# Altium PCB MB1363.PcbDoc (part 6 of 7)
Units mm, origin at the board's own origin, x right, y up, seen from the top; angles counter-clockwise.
Board outline 70 x 133.34 mm, 6 copper layers (Top Layer, Signal Layer 1, Signal Layer 2, Signal Layer 3, Signal Layer 4, Bottom Layer), stack 1.57 mm thick; 356 components, 294 nets, 1448 pads, 1107 vias.
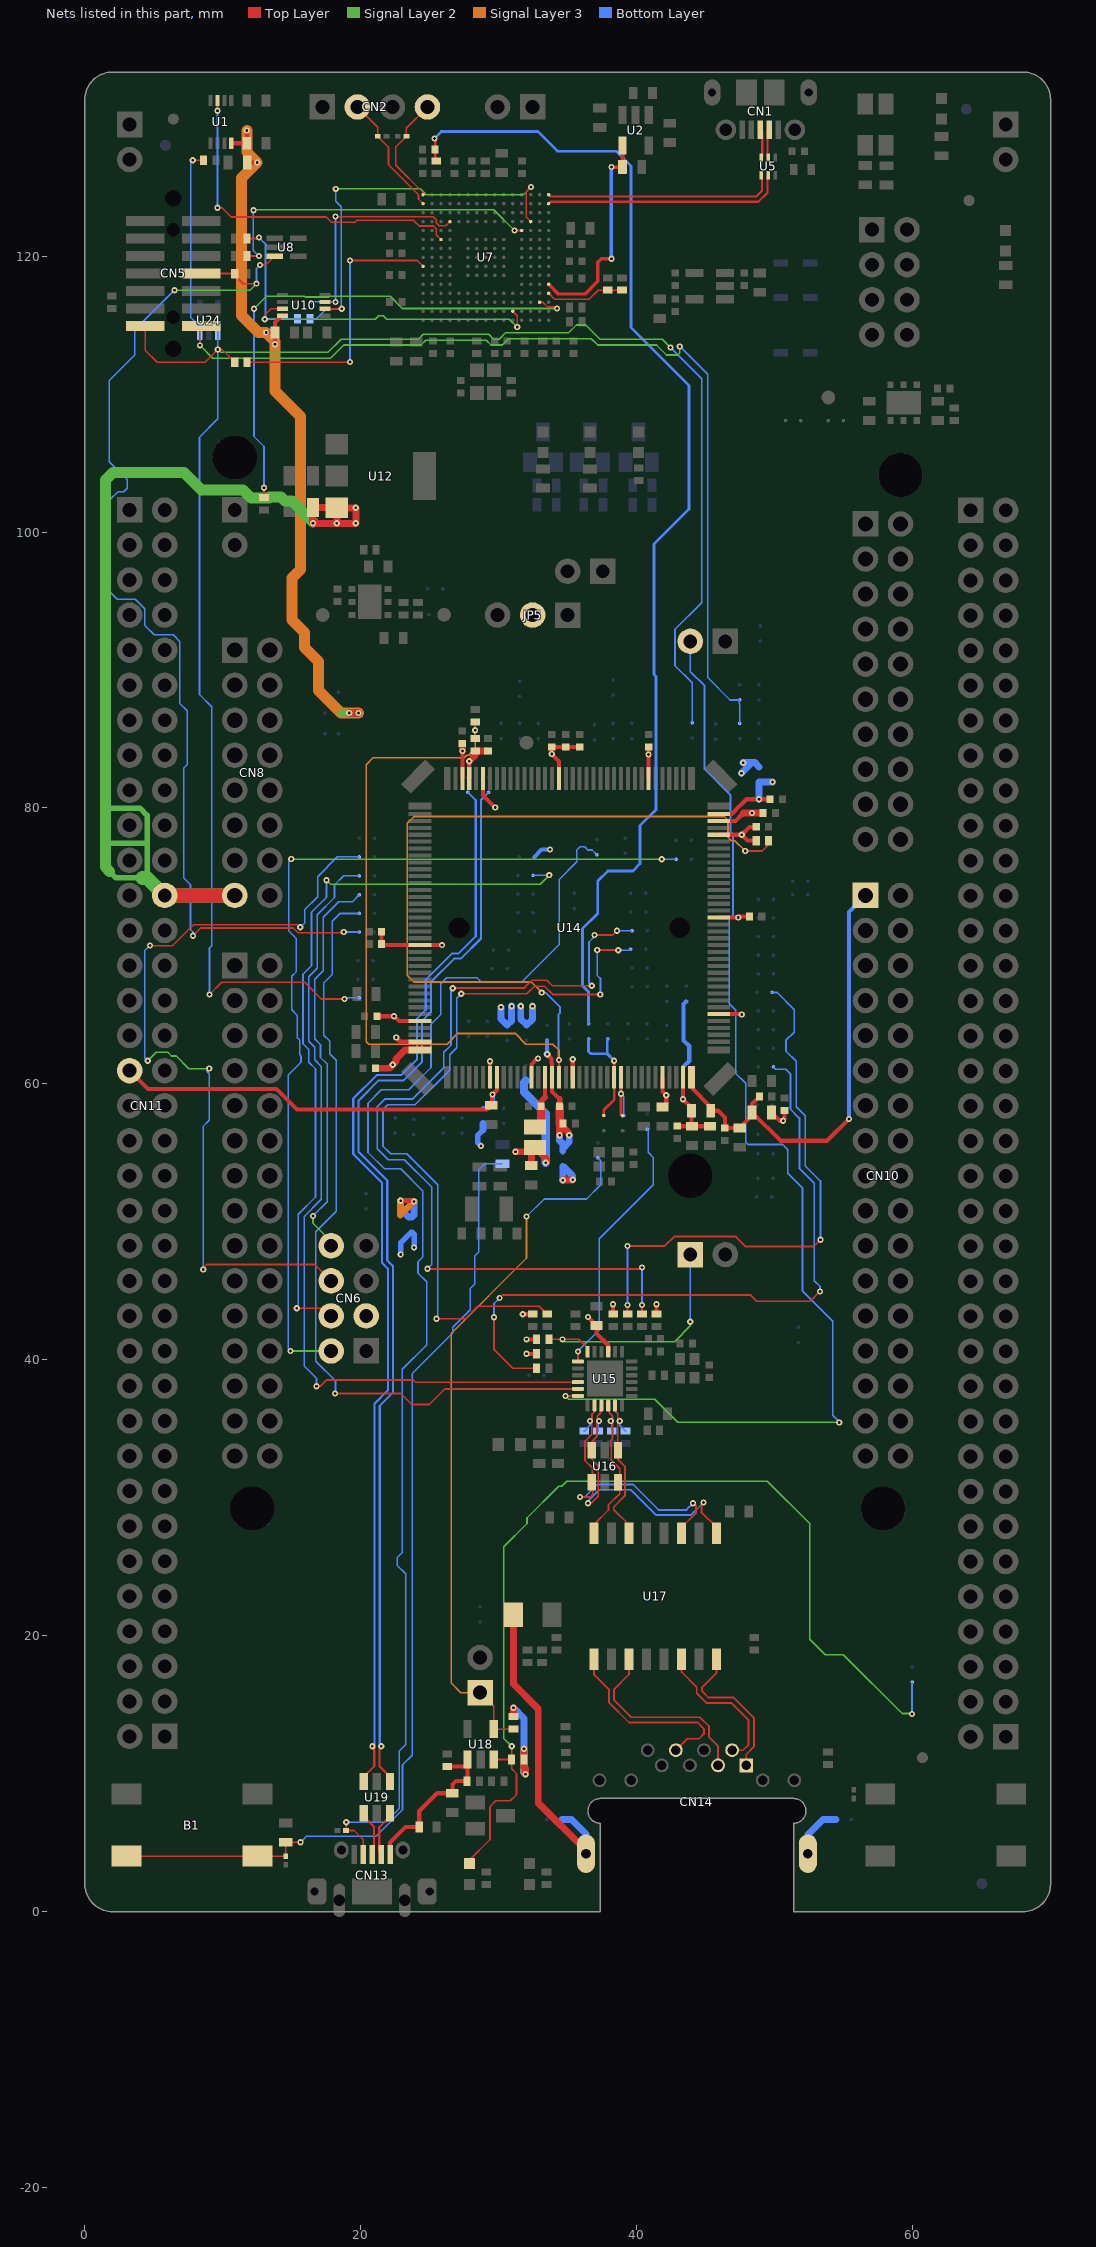
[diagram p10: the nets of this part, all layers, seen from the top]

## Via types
v1: diameter 0.45, hole 0.2, Top Layer to Bottom Layer, tented both sides, 1098 vias
v2: diameter 0.6, hole 0.3, Top Layer to Bottom Layer, tented both sides, 9 vias

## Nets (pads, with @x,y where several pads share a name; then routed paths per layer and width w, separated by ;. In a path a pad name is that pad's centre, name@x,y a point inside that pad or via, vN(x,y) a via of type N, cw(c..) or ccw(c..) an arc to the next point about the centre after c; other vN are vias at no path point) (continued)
PH0: SB3.1 SB71.1 SB72.1 U14.25 | length 8.4
  Top Layer w0.2: SB3.1@37.616,57.704 37.616,58.091 38.366,58.841 U14.25@38.366,60.479 v1(38.366,61.679)
  Bottom Layer w0.2: SB72.1@36.516,63.254 36.516,62.354 36.691,62.179 37.866,62.179 ; SB71.1@37.916,63.254 37.866,63.204 37.866,62.179 ; v1(38.366,61.679) 37.866,62.179
PH1: SB4.1 SB90.1 U14.26 | length 4.6
  Top Layer w0.127: U14.26@38.816,60.429 U14.26@38.866,60.479 ; 38.866,57.804 SB4.1@38.966,57.704
  Top Layer w0.2: 38.866,57.804 U14.26@38.866,60.479
  Signal Layer 2 w0.127: v1@38.866,59.176 v1(38.866,59.279)
  Bottom Layer w0.127: v1(38.866,59.279) 39.066,59.079 SB90.1@39.066,57.704
RD_N: R79.1 U15.22 U16.6 U17.8 | length 11.5
  Top Layer w0.11: 38.166,32.705 38.166,34.204
  Top Layer w0.13: U17.8@36.901,27.434 36.966,27.499 36.966,28.116 37.959,29.109 37.959,29.484 38.766,30.291 38.766,31.004 U16.6@38.641,31.129 38.766,31.254 38.766,32.105 38.166,32.705 ; U15.22@37.941,36.679 38.009,36.611 38.009,36.161 38.241,35.929 38.241,35.679 v1(38.116,35.554) 38.25,35.42 38.25,34.288 38.166,34.204
  Bottom Layer w0.13: R79.1@38.191,34.829 38.191,35.479 v1(38.116,35.554) v1@38.25,35.554
RD_P: R78.1 U15.23 U16.1 U17.6 | length 11.4
  Top Layer w0.13: U15.23@38.441,36.679 38.391,36.629 38.391,36.319 38.623,36.087 38.623,35.697 v1(38.766,35.554) 38.632,35.42 38.632,33.438 U16.1@38.641,33.429 38.641,32.781 39.148,32.274 39.148,30.133 38.341,29.326 38.341,29.134 39.441,28.034 U17.6@39.441,27.434
  Bottom Layer w0.13: v1(38.766,35.554) 38.766,35.254 R78.1@39.191,34.829
RMII_CRS_DV: R44.1 SB52.2 | length 54.4
  Top Layer w0.127: v1(25.491,42.979) 27.59,42.979 28.49,43.879 32.941,43.879 R44.1@33.516,43.304 ; v1(27.291,66.529) 32.041,66.529 32.591,67.079 33.316,67.079 33.914,66.481 34.418,66.481 34.42,66.479 v1(37.366,66.479) ; v1(37.141,69.704) 38.642,69.704 v1(38.667,69.68)
  Bottom Layer w0.127: v1(25.491,42.979) 25.572,43.06 25.572,52.698 23.341,54.929 22.166,54.929 21.616,55.479 21.616,58.152 21.943,58.479 23.935,58.479 26.443,60.987 26.443,62.102 26.966,62.626 26.966,66.204 v1(27.291,66.529) ; v1(37.141,69.704) 37.141,67.854 37.386,67.609 37.386,66.498 v1(37.366,66.479) ; v1(38.667,69.68) 39.492,69.68 SB52.2@39.566,69.754
RMII_MDC: SB84.1 U15.13 | length 19.3
  Top Layer w0.127: U15.13@35.741,39.879 v1(35.741,40.604)
  Bottom Layer w0.127: v1(35.741,40.604) 37.291,42.154 37.291,48.779 41.205,52.693 41.205,54.665 40.841,55.029 40.841,56.629 SB84.1@40.766,56.704
RMII_MDIO: JP7.1 R50.1 U15.12 | length 18.3
  Top Layer w0.127: R50.1@33.641,41.479 v1(34.616,41.479) 35.787,41.479 36.441,40.825 U15.12@36.441,40.579
  Signal Layer 2 w0.102: v1(34.616,41.479) 34.775,41.32 42.758,41.32 43.886,42.449 v1(43.886,42.749)
  Bottom Layer w0.127: v1(43.886,42.749) JP7.1@43.886,47.624
RMII_REF_CLK: R52.1 SB80.2 | length 49.4
  Top Layer w0.127: v1(29.666,43.079) 29.666,40.729 31.016,39.379 R52.1@32.741,39.379 ; v1(30.066,44.479) 30.274,44.687 48.261,44.687 48.698,44.25 52.587,44.25 v1(53.291,44.954)
  Bottom Layer w0.127: v1(29.666,43.079) 29.666,44.079 v1(30.066,44.479) ; SB80.2@49.916,61.229 50.093,61.052 50.814,61.052 51.141,60.725 51.141,58.176 51.798,57.52 51.798,53.87 52.873,52.795 52.873,45.738 53.286,45.324 53.286,44.959 v1(53.291,44.954)
RMII_RXD0: R47.1 SB63.1 | length 39.8
  Top Layer w0.127: R47.1@39.341,43.304 v1(39.341,43.979) ; v1(39.341,48.254) 42.041,48.254 42.716,48.929 47.191,48.929 47.918,48.202 52.814,48.202 v1(53.316,48.704)
  Bottom Layer w0.127: v1(39.341,43.979) v1(39.341,48.254) ; SB63.1@49.816,66.629 50.17,66.629 51.414,65.384 51.414,63.753 50.816,63.155 50.816,62.383 51.568,61.631 51.568,58.353 52.225,57.696 52.225,54.047 53.318,52.954 53.318,48.705 v1(53.316,48.704)
RMII_RXD1: R48.1 SB48.1 | length 62.5
  Top Layer w0.127: v1(24.841,46.604) 24.868,46.577 40.265,46.577 40.391,46.704 v1(40.391,46.679) ; v1(26.666,66.929) 26.693,66.956 31.864,66.956 32.414,67.506 33.493,67.506 33.895,67.104 v1(36.741,67.104) ; v1(36.951,70.78) 38.244,70.78 v1(38.568,71.104) ; R48.1@40.391,43.304 v1(40.391,43.979)
  Bottom Layer w0.127: v1(24.841,46.604) 25.145,46.908 25.145,52.521 23.164,54.502 21.989,54.502 21.189,55.302 21.189,58.329 21.766,58.906 23.758,58.906 26.016,61.164 26.016,62.279 26.539,62.803 26.539,66.802 v1(26.666,66.929) ; v1(36.741,67.104) 36.541,67.304 36.541,70.279 36.951,70.689 v1(36.951,70.78) ; v1(38.568,71.104) SB48.1@39.666,71.104 ; v1(40.391,43.979) v1(40.391,46.679)
RMII_TX_EN: SB36.1 U15.16 | length 59.6
  Top Layer w0.127: v1(16.791,38.079) 17.062,38.079 17.509,38.526 23.819,38.526 23.966,38.379 U15.16@35.741,38.379
  Bottom Layer w0.127: v1(16.791,38.079) 16.791,38.656 15.896,39.552 15.896,50.382 17.141,51.627 17.141,61.257 16.661,61.737 16.661,62.659 16.236,63.084 16.236,67.761 16.851,68.376 16.851,72.26 18.099,73.508 18.099,74.412 18.766,75.079 SB36.1@19.891,75.079
RMII_TXD0: SB46.1 U15.17 | length 56.7
  Top Layer w0.127: v1(18.141,37.554) 22.891,37.554 23.691,36.754 24.966,36.754 26.091,37.879 U15.17@35.741,37.879
  Bottom Layer w0.127: v1(18.141,37.554) 18.166,37.579 18.166,38.479 16.743,39.902 16.743,49.273 18.228,50.758 18.228,61.707 17.748,62.187 17.748,63.109 17.323,63.534 17.323,67.311 17.938,67.926 17.938,71.775 18.516,72.354 SB46.1@19.891,72.354
RMII_TXD1: JP6.2 U15.18 | length 84.4
  Top Layer w0.127: v1(34.841,37.379) U15.18@35.741,37.379
  Signal Layer 2 w0.102: v1(34.841,37.379) 35.091,37.129 41.316,37.129 42.066,36.379 42.991,35.454 v1(54.691,35.454)
  Bottom Layer w0.127: JP6.2@43.886,92.074 43.886,89.884 44.925,88.845 44.925,82.819 46.793,80.95 46.793,78.277 46.991,78.079 46.991,72.267 46.716,71.991 46.716,65.802 47.189,65.329 47.189,60.752 47.908,60.033 47.908,55.778 48.073,55.612 50.567,55.612 50.951,55.229 50.951,53.519 52.026,52.444 52.026,44.97 54.218,42.778 54.218,35.977 54.716,35.479 v1(54.691,35.454)
RX_N: CN14.6 U17.9 | length 14.1
  Top Layer w0.13: U17.9@36.901,18.284 36.901,17.199 37.984,16.116 37.984,15.161 39.441,13.704 44.426,13.704 44.871,13.259 44.871,12.884 44.516,12.529 43.668,12.529 CN14.6@42.839,11.7
RX_P: CN14.3 U17.11 | length 14.2
  Top Layer w0.13: U17.11@39.441,18.284 39.441,17.191 38.366,16.116 38.366,15.319 39.599,14.086 44.584,14.086 45.253,13.417 45.253,12.642 45.899,11.996 CN14.3@45.899,10.6
SHGND: C90.1 CN14.SH1 CN14.SH2 SB101.1 SB102.1 | length 27.2
  Top Layer w0.5: C90.1@31.066,21.529 31.066,16.484 32.866,14.684 32.866,7.884 CN14.SH2@36.35,4.4
  Bottom Layer w0.45: CN14.SH2@36.25,4.2 CN14.SH2@36.329,4.2
  Bottom Layer w0.5: SB101.1@34.575,6.675 35.275,6.675 36.329,5.621 CN14.SH2@36.329,4.2 ; CN14.SH2@36.25,4.2 CN14.SH2@36.3,4.15 ; CN14.SH1@52.409,4.2 52.409,5.584 53.5,6.675 SB102.1@54.45,6.675 ; CN14.SH1@52.425,4.225 CN14.SH1@52.425,4.45
SMPS_EN: CN6.4 SB35.1 | length 53.1
  Top Layer w0.12: v1(15.366,43.729) 17.301,43.729 CN6.4@17.851,43.179
  Signal Layer 2 w0.12: v1(17.516,74.754) 17.801,74.469 33.006,74.469 v1(33.666,75.129)
  Bottom Layer w0.12: v1(15.366,43.729) 15.366,43.754 15.472,43.86 15.472,50.558 16.717,51.803 16.717,61.081 16.237,61.561 16.237,62.483 15.812,62.908 15.812,67.937 16.427,68.552 16.427,72.435 17.516,73.524 v1(17.516,74.754) ; SB35.1@32.491,75.104 32.516,75.129 v1(33.666,75.129)
SMPS_PG: CN6.8 SB42.1 | length 28.7
  Signal Layer 2 w0.12: v1(16.541,50.429) 16.541,49.887 17.851,48.577 CN6.8@17.851,48.259
  Bottom Layer w0.12: v1(16.541,50.429) 17.564,51.452 17.564,61.432 17.084,61.912 17.084,62.834 16.659,63.259 16.659,67.586 17.274,68.201 17.274,72.085 18.398,73.209 19.396,73.209 SB42.1@19.891,73.704
SMPS_SW: CN6.6 SB33.1 | length 58.2
  Top Layer w0.12: v1(4.716,70.029) 4.701,70.014 6.353,70.014 7.878,71.539 15.431,71.539 v1(15.616,71.354) ; v1(8.586,46.549) 8.586,46.665 8.828,46.907 16.663,46.907 CN6.6@17.851,45.719
  Signal Layer 2 w0.12: v1(4.566,61.679) 5.166,62.279 6.029,62.279 6.284,62.024 6.621,62.024 7.541,61.104 v1(9.016,61.104)
  Bottom Layer w0.12: v1(4.566,61.679) 4.351,61.894 4.351,69.664 v1(4.716,70.029) ; v1(8.586,46.549) 8.571,46.549 8.571,56.911 9.021,57.361 9.021,60.739 8.836,60.924 v1(9.016,61.104) ; v1(15.616,71.354) 15.616,71.329 15.947,71.66 15.947,72.634 16.871,73.558 16.871,75.021 18.304,76.454 SB33.1@19.891,76.454
SMPS_V1: CN6.2 SB34.1 | length 67.7
  Signal Layer 2 w0.12: v1(14.916,40.628) 14.927,40.639 CN6.2@17.851,40.639 ; v1(14.966,76.304) 14.991,76.279 v1(41.816,76.279)
  Bottom Layer w0.12: v1(14.916,40.628) 14.916,40.639 14.751,40.804 14.751,60.641 15.671,61.561 15.671,62.031 15.568,62.134 15.568,63.174 15.403,63.339 15.403,64.955 14.998,65.361 14.998,67.804 15.336,68.142 15.336,70.519 14.781,71.074 14.781,76.094 14.966,76.279 v1(14.966,76.304) ; v1(41.816,76.279) SB34.1@42.866,76.279
STLK_MCO: C5.2 R5.2 SB72.2 | length 85.7
  Top Layer w0.2: v1(25.341,128.529) 25.391,128.479 C5.2@25.391,127.729 25.391,126.954 R5.2@25.466,126.879
  Bottom Layer w0.2: v1(25.341,128.529) 25.841,129.029 32.841,129.029 34.266,127.604 38.516,127.604 39.591,126.529 39.591,114.829 43.791,110.629 43.791,101.654 41.254,99.117 41.254,89.681 41.4,89.535 41.4,79.868 40.249,78.717 40.249,75.962 39.724,75.437 37.909,75.437 37.181,74.71 37.181,72.36 36.078,71.256 36.078,67.112 36.516,66.673 SB72.2@36.516,64.354
STLK_SWCLK: CN2.2 U3.1 U7.A14 | length 9
  Top Layer w0.12: CN2.2@19.756,130.809 21.229,129.336 U3.1@21.229,128.679 21.229,128.672 22.016,127.884 22.016,126.615 24.184,124.447 24.184,124.136 U7.A14@24.516,123.804
STLK_SWDIO: CN2.4 U4.1 U7.A15 | length 8.1
  Top Layer w0.12: U7.A15@24.516,124.454 24.516,124.604 22.541,126.579 22.541,127.909 23.303,128.672 U4.1@23.303,128.679 23.303,129.276 CN2.4@24.836,130.809
STLK_VCP_RX: U1.3 U7.C10 | length 25.3
  Top Layer w0.12: v1(9.616,123.504) 9.941,123.504 10.616,122.829 17.491,122.829 17.876,122.444 19.566,122.444 19.731,122.609 23.811,122.609 24.241,122.179 25.272,122.179 25.471,121.98 25.471,121.549 U7.C10@25.816,121.204 ; v1(9.616,130.529) U1.3@9.616,131.279
  Bottom Layer w0.12: v1(9.616,123.504) v1(9.616,130.529)
STLK_VCP_TX: R23.1 U7.A7 | length 20.3
  Top Layer w0.12: R23.1@11.766,112.304 19.191,112.304 v1(19.216,112.329) ; v1(19.216,119.679) 24.091,119.679 U7.A7@24.516,119.254
  Bottom Layer w0.12: v1(19.216,112.329) v1(19.216,119.679)
T_NRSTa: R29.1 U7.P3 | length 38.1
  Top Layer w0.12: R29.1@12.991,102.504 v1(12.991,103.204) ; U7.P3@32.966,116.654 33.185,116.654 33.53,116.309 34.111,116.309 v1(34.216,116.204)
  Signal Layer 2 w0.12: v1(12.266,116.179) 13.171,117.084 15.922,117.084 15.972,117.034 17.683,117.034 17.733,117.084 22.134,117.084 23.014,116.204 v1(34.216,116.204)
  Bottom Layer w0.12: v1(12.266,116.179) 12.266,106.929 12.991,106.204 v1(12.991,103.204)
T_PWR_EN: R7.1 U2.4 U7.R5 | length 15.7
  Top Layer w0.25: U7.R5@33.616,117.954 34.316,117.254 36.266,117.254 37.191,118.179 37.191,119.554 37.441,119.804 v1(38.166,119.804) ; v1(38.166,126.454) 38.969,126.454 R7.1@38.973,126.459
  Top Layer w0.3: U2.4@38.966,128.014 38.973,128.006 R7.1@38.973,126.459
  Bottom Layer w0.25: v1(38.166,119.804) v1(38.166,126.454)
T_PWR_EXT: R14.2 R15.2 U7.R4 | length 5.8
  Top Layer w0.12: U7.R4@33.616,117.304 34.036,116.884 36.571,116.884 37.216,117.529 R14.2@37.891,117.529 R15.2@38.941,117.529
T_SWCLKa: R11.1 U7.M11 | length 24.4
  Top Layer w0.12: R11.1@11.766,120.004 v1(12.616,120.004) ; v1(31.141,121.854) U7.M11@31.666,121.854
  Signal Layer 2 w0.12: v1(12.216,123.329) 12.241,123.354 29.641,123.354 v1(31.141,121.854)
  Bottom Layer w0.12: v1(12.216,123.329) 12.216,121.552 12.211,121.547 12.211,120.409 v1(12.616,120.004)
T_SWDIO_IN: R70.2 U7.N12 U10.2 | length 30
  Top Layer w0.12: U10.2@17.416,116.179 v1(18.616,116.179) ; U7.N12@32.316,122.504 31.991,122.829 31.991,124.679 32.316,125.004 v1(32.341,125.004)
  Signal Layer 2 w0.12: v1(18.186,124.874) 24.321,124.874 24.741,124.454 31.791,124.454 v1(32.341,125.004)
  Bottom Layer w0.12: R70.2@16.316,115.454 16.791,115.454 17.516,116.179 v1(18.616,116.179) 18.591,116.204 18.591,123.581 18.186,123.986 v1(18.186,124.874)
T_SWDIOa: R10.2 R70.1 U7.L2 U10.7 | length 31.3
  Top Layer w0.12: R10.2@11.766,121.279 12.616,121.279 v1(12.616,121.354) ; v1(13.041,115.429) 13.041,115.729 13.491,116.179 U10.7@14.316,116.179 ; U7.L2@31.016,116.004 31.341,115.679 v1(31.341,114.854)
  Signal Layer 2 w0.12: v1(13.041,115.429) 21.043,115.429 21.298,115.684 21.634,115.684 21.889,115.429 30.766,115.429 v1(31.341,114.854)
  Bottom Layer w0.12: v1(12.616,121.354) 13.141,120.829 13.096,120.784 13.096,115.484 v1@13.066,115.454 ; v1(13.041,115.429) v1@13.066,115.454 ; R70.1@15.416,115.454 v1@13.066,115.454
T_SWO: CN5.8 R13.1 SB50.1 U8.3 | length 80.1
  Top Layer w0.12: v1(7.841,70.729) 8.411,71.299 15.098,71.299 15.448,70.949 18.711,70.949 v1(18.766,71.004) ; CN5.8@8.453,118.744 10.851,118.744 R13.1@10.866,118.729 10.866,118.629 11.491,118.004 v1(12.441,118.004) ; v1(12.691,119.354) 13.116,119.354 U8.3@13.766,120.004
  Signal Layer 2 w0.12: v1(6.491,117.529) 11.966,117.529 v1(12.441,118.004)
  Bottom Layer w0.12: v1(6.491,117.529) 3.616,114.654 3.616,112.829 1.766,110.979 1.766,105.104 3.066,103.804 3.066,103.179 2.816,102.929 2.403,102.929 1.766,102.292 1.766,95.704 2.341,95.129 3.659,95.129 4.351,94.437 4.351,93.219 5.026,92.544 6.401,92.544 6.891,92.054 6.891,87.555 7.413,87.033 7.413,83.145 7.166,82.898 7.166,74.919 7.653,74.432 7.653,71.192 7.841,71.004 v1(7.841,70.729) ; v1(12.441,118.004) 12.441,119.104 v1(12.691,119.354) ; v1(18.766,71.004) SB50.1@19.891,71.004
T_SWOa: SB5.1 U7.D12 U10.3 | length 17.6
  Top Layer w0.12: U10.3@17.416,116.679 v1(18.166,116.679) ; v1(18.166,122.879) 18.191,122.854 19.366,122.854 ; 19.366,122.849 25.252,122.849 25.471,122.63 25.471,122.418 25.69,122.199 26.161,122.199 U7.D12@26.466,122.504
  Bottom Layer w0.12: SB5.1@16.391,116.679 v1(18.166,116.679) v1(18.166,122.879)
T_VCP_RX: CN5.13 R23.2 SB17.2 SB64.1 U24.1 | length 134
  Top Layer w0.12: CN5.13@4.389,114.934 4.389,113.156 5.241,112.304 8.716,112.304 v1(9.641,113.229) 9.941,113.229 R23.2@10.866,112.304 ; v1(9.041,66.479) 9.915,67.354 15.945,67.354 17.145,66.154 v1(18.816,66.154)
  Signal Layer 2 w0.12: v1(9.641,113.229) 9.851,113.019 17.631,113.019 18.591,113.979 24.191,113.979 24.536,114.324 29.271,114.324 29.616,113.979 30.041,113.979 30.496,114.434 35.061,114.434 35.636,115.009 36.313,115.009 37.343,113.979 41.845,113.979 v1(42.443,113.382)
  Bottom Layer w0.12: v1@9.031,66.479 9.031,69.852 9.198,70.019 9.198,87.334 8.316,88.216 8.316,106.879 9.641,108.204 v1(9.641,113.229) U24.1@9.641,114.504 ; v1@19.016,66.229 SB64.1@19.891,66.229 ; v1(42.443,113.382) 44.721,111.103 44.721,94.884 42.781,92.944 42.781,90.314 44.025,89.07 SB17.2@44.025,86.175
T_VCP_TX: CN5.14 R3.1 SB12.1 SB16.2 U24.3 | length 82.6
  Top Layer w0.12: v1(7.816,126.954) R3.1@8.591,126.954 ; v1(8.341,113.529) 8.341,114.812 CN5.14@8.458,114.929
  Signal Layer 2 w0.12: v1(8.341,113.529) 9.271,112.599 17.805,112.599 18.765,113.559 24.365,113.559 24.71,113.904 29.097,113.904 29.442,113.559 30.261,113.559 30.716,114.014 36.714,114.014 37.169,113.559 41.436,113.559 42.166,112.829 42.975,112.829 43.116,112.97 v1(43.116,113.454)
  Bottom Layer w0.12: v1(7.816,126.954) 7.666,126.804 7.666,115.554 8.341,114.879 U24.3@8.341,114.504 v1(8.341,113.529) ; v1(43.116,113.454) 45.141,111.429 45.141,89.453 46.765,87.829 SB12.1@47.466,87.829 47.441,87.804 47.441,87.529 47.466,87.504 SB16.2@47.466,86.129
TD_N: R81.1 U15.20 U16.4 U17.3 | length 21.1
  Top Layer w0.13: v1@36.05,30.05 36.622,30.05 36.816,30.244 36.816,31.054 U16.4@36.741,31.129 36.801,31.189 36.801,32.13 36.256,32.675 36.256,34.105 36.75,34.6 36.75,35.42 v1(36.616,35.554) 36.759,35.697 36.759,36.062 36.991,36.294 36.991,36.629 U15.20@36.941,36.679 ; U17.3@43.251,27.434 43.251,27.839 44.309,28.897 44.309,29.416 v1@44.1,29.625
  Bottom Layer w0.13: v1(35.9,30.05) 36.23,30.05 37.139,30.96 39.74,30.96 41.58,29.12 43.607,29.12 v1(44.091,29.604) ; R81.1@36.191,34.829 36.616,35.254 v1(36.616,35.554)
TD_P: R80.1 U15.21 U16.3 U17.1 | length 21.6
  Top Layer w0.11: 37.216,30.379 37.216,31.815
  Top Layer w0.13: v1@36.475,29.6 36.712,29.6 37.216,30.104 37.216,30.379 ; 37.216,31.815 37.216,32.332 36.741,32.807 U16.3@36.741,33.429 36.741,34.05 37.132,34.441 37.132,35.42 v1(37.266,35.554) 37.141,35.679 37.141,35.904 37.373,36.136 37.373,36.611 U15.21@37.441,36.679 ; v1@44.837,29.637 44.691,29.491 44.691,28.954 45.791,27.854 U17.1@45.791,27.434
  Bottom Layer w0.13: v1(36.466,29.604) 36.466,29.746 37.297,30.578 39.582,30.578 41.422,28.738 43.925,28.738 v1(44.841,29.654) ; R80.1@37.191,34.829 37.191,35.479 v1(37.266,35.554)
TX_N: CN14.2 U17.14 | length 10.6
  Top Layer w0.13: U17.14@43.251,18.284 43.251,17.374 44.359,16.266 44.359,15.821 45.051,15.129 46.866,15.129 48.116,13.879 48.116,13.014 48.114,13.012 48.114,12.106 47.708,11.7 CN14.2@46.919,11.7
TX_P: CN14.1 U17.16 | length 11
  Top Layer w0.13: U17.16@45.791,18.284 45.791,17.316 44.741,16.266 44.741,15.979 45.209,15.511 47.024,15.511 48.498,14.037 48.498,12.856 48.496,12.854 48.496,11.947 47.939,11.39 CN14.1@47.939,10.6
USB_DEV_HS_CN_N: CN1.2 U5.5 | length 2.1
  Top Layer w0.155: U5.5@49.541,127.154 49.482,127.213 49.482,129.023 CN1.2@49.616,129.158
USB_DEV_HS_CN_P: CN1.3 U5.6 | length 2.1
  Top Layer w0.155: CN1.3@48.966,129.158 49.1,129.023 49.1,127.213 U5.6@49.041,127.154
USB_DEV_HS_N: U5.2 U7.R14 | length 17.5
  Top Layer w0.155: U7.R14@33.616,123.804 33.751,123.938 48.814,123.938 49.416,124.54 49.472,124.596 49.472,125.785 U5.2@49.541,125.854
USB_DEV_HS_P: U5.1 U7.R15 | length 16.8
  Top Layer w0.155: U7.R15@33.616,124.454 33.751,124.319 48.657,124.319 49.091,124.754 49.091,125.804 U5.1@49.041,125.854
USB_FS_CN_N: CN13.2 U19.6 | length 3.4
  Top Layer w0.155: CN13.2@21.473,4.139 21.338,4.273 21.338,6.122 22.116,6.9 U19.6@22.116,7.129
USB_FS_CN_P: CN13.3 U19.4 | length 3.4
  Top Layer w0.155: U19.4@20.216,7.129 20.216,6.9 20.957,6.158 20.957,4.273 CN13.3@20.823,4.139
USB_FS_ID: CN13.4 SB29.2 U22.1 | length 93.8
  Top Layer w0.12: v1(18.941,6.479) 18.941,5.891 U22.1@18.928,5.879 19.516,5.879 20.173,5.222 CN13.4@20.173,4.139
  Bottom Layer w0.12: v1(18.941,6.479) 21.791,6.479 22.786,7.474 22.786,11.647 23.251,12.112 23.251,24.479 22.646,25.084 22.646,25.666 23.011,26.031 23.011,39.303 24.776,41.068 24.776,45.654 24.151,46.279 24.151,47.103 24.482,47.433 24.482,52.246 22.889,53.838 21.714,53.838 20.526,55.027 20.526,58.604 21.491,59.569 23.483,59.569 25.096,61.182 25.096,64.321 25.801,65.026 25.801,67.253 26.242,67.694 28.426,67.694 28.716,67.404 31.691,67.404 34.376,70.089 34.376,74.803 35.661,76.088 35.661,76.949 35.896,77.184 36.234,77.184 36.464,76.954 36.766,76.954 SB29.2@37.116,76.604
USB_FS_N: SB26.2 U19.1 | length 78.8
  Top Layer w0.155: v1(21.491,11.979) 21.357,11.844 21.357,10.538 22.116,9.779 U19.1@22.116,9.429
  Bottom Layer w0.155: v1(21.491,11.979) 21.372,12.098 21.372,36.66 22.347,37.635 22.347,46.762 21.916,47.193 21.916,52.993 19.841,55.068 19.841,58.779 21.316,60.254 23.105,60.254 24.447,61.596 24.447,64.571 25.091,65.215 25.091,67.39 26.78,69.079 27.255,69.079 28.716,70.54 28.716,80.579 SB26.2@29.266,81.129
USB_FS_OVCR: LD7.2 R64.1 SB100.1 U18.3 | length 75.1
  Top Layer w0.12: LD7.2@27.866,3.479 27.866,3.729 29.366,5.229 29.366,7.604 29.791,8.029 30.841,8.029 31.291,8.479 31.291,10.004 30.941,10.354 R64.1@30.941,11.024 ; U18.3@29.641,11.024 R64.1@30.941,11.024 ; v1(30.941,11.979) R64.1@30.941,11.024
  Signal Layer 2 w0.12: v1(30.941,11.979) v1@30.944,11.981 ; v1@31,11.925 v1@30.944,11.981 ; v1(59.95,14.325) v1@59.921,14.354 ; v1@59.95,14.354 v1@59.921,14.354 ; v1@30.944,11.981 30.375,12.55 30.375,26.45 32.05,28.125 32.05,28.525 34.359,30.834 34.558,30.834 34.924,31.2 49.475,31.2 52.55,28.125 52.55,19.752 53.677,18.625 54.975,18.625 59.246,14.354 v1@59.921,14.354
  Bottom Layer w0.12: v1(59.95,14.325) 59.95,16.6 SB100.1@59.975,16.625 59.975,14.35 v1(59.95,14.325)
USB_FS_P: SB27.2 U19.3 | length 78.8
  Top Layer w0.155: U19.3@20.216,9.429 20.216,9.779 20.975,10.538 20.975,11.844 v1(20.841,11.979)
  Bottom Layer w0.155: v1(20.841,11.979) 20.991,12.129 20.991,36.818 21.966,37.793 21.966,46.604 21.535,47.035 21.535,52.835 19.46,54.91 19.46,58.937 21.158,60.635 22.947,60.635 24.066,61.754 24.066,64.729 24.71,65.373 24.71,67.548 26.622,69.46 27.097,69.46 28.335,70.698 28.335,80.56 SB27.2@27.766,81.129
USB_FS_PWR_EN: JP8.1 R59.1 SB91.2 U18.4 | length 51.3
  Top Layer w0.12: JP8.1@28.646,15.874 29.641,14.879 U18.4@29.641,13.224 29.646,13.229 R59.1@31.066,13.229
  Signal Layer 3 w0.12: JP8.1@28.646,15.874 27.246,15.874 26.571,16.549 26.571,41.93 32.016,47.375 v1(32.016,50.378)
  Bottom Layer w0.12: v1(32.016,50.378) 33.292,51.655 36.367,51.655 37.391,52.679 37.391,54.429 SB91.2@37.191,54.629
USB_FS_VBUS: C91.2 CN13.1 R63.1 R65.1 U18.1 U21.1 | length 12.4
  Top Layer w0.3: CN13.1@22.123,4.139 22.123,5.011 23.241,6.129 U21.1@24.241,6.129 24.241,7.279 25.541,8.579 C91.2@26.641,8.579 26.641,9.204 26.891,9.454 R65.1@27.691,9.454 27.741,9.504 U18.1@27.741,10.629 ; R63.1@26.266,10.529 27.641,10.529 U18.1@27.741,10.629 ; U18.1@27.741,11.024 U18.1@27.741,10.629
VBAT: C63.2 CN11.33 SB83.2 U14.8 | length 31.2
  Top Layer w0.3: CN11.33@3.246,60.959 4.591,59.614 13.901,59.614 15.381,58.134 29.146,58.134 C63.2@29.466,58.454 29.516,58.504 29.516,59.189 v1(29.556,59.229) 29.864,59.537 29.864,60.476 U14.8@29.866,60.479
  Bottom Layer w0.3: SB83.2@28.866,58.229 29.241,58.229 29.564,58.551 29.564,59.221 v1(29.556,59.229)
VCAP: C54.2 C58.2 R35.1 SB75.1 U14.68 U14.103 U14.140 | length 13
  Top Layer w0.3: C58.2@21.166,64.904 v1(22.416,64.904) 22.766,64.554 U14.140@24.291,64.554 ; U14.103@28.866,82.129 28.866,80.904 v1(29.741,80.029) ; U14.68@45.941,78.054 v1(47.616,78.054) ; R35.1@48.666,77.629 48.041,77.629 v1(47.616,78.054) ; C54.2@48.666,78.629 48.191,78.629 v1(47.616,78.054)
  Bottom Layer w0.5: 31.594,64.681 31.594,64.701 ; v1(31.594,65.629) 31.594,64.701 ; SB75.1@32.005,64.29 31.594,64.701 ; SB75.1@32.015,64.253 32.444,64.681 v1(32.444,65.629)
VDD_LDO: C51.1 C53.1 R34.1 SB25.1 SB76.1 U14.70 U14.105 U14.143 | length 13.8
  Top Layer w0.3: v1(22.566,63.353) 22.865,63.054 U14.143@24.291,63.054 ; U14.105@27.866,82.129 v1(27.866,83.379) 28.116,83.629 ; U14.70@45.941,79.054 47.166,79.054 47.691,79.579
  Top Layer w0.5: 28.116,83.629 28.291,83.804 R34.1@28.291,84.129 C51.1@29.216,84.129 ; 47.691,79.579 47.741,79.629 v1(48.366,79.629) C53.1@49.166,79.629
  Bottom Layer w0.5: v1(30.171,65.554) 30.171,64.698 SB76.1@30.616,64.253 30.925,64.561 30.925,65.617 v1(30.936,65.629) ; v1(47.604,82.516) 48.366,83.279 ; v1(47.719,83.279) 48.366,83.279 ; SB25.1@48.866,82.979 48.566,83.279 48.366,83.279
VDD_MCU: C4.1 C26.1 C46.2 C47.2 C48.2 C49.2 C50.2 C52.2 C55.2 C56.2 C57.2 C59.2 C62.1 C67.2 C79.2 JP5.2 R4.2 R40.1 R43.2 R46.2 R49.2 R50.2 R51.2 R59.2 R64.2 SB14.1 SB25.2 SB32.2 SB83.1 SB92.2 SB97.2 U1.8 U10.8 U14.7 U14.13 U14.19 U14.32 U14.42 U14.56 U14.71 U14.79 U14.92 U14.106 U14.129 U14.144 U15.9 | length 125.9
  Top Layer w0.3: U1.8@10.616,128.179 C4.1@11.741,128.179 v1(11.741,129.104) ; R4.2@11.766,126.779 v1(12.491,126.779) ; v1(13.141,114.454) C26.1@13.791,114.454 ; v1(13.791,113.604) C26.1@13.791,114.454 ; U10.8@14.316,115.679 14.283,115.679 13.791,115.187 C26.1@13.791,114.454 ; C56.2@21.516,71.029 C57.2@21.516,70.129 21.516,70.054 U14.129@24.291,70.054 v1(25.881,70.054) ; v1(22.891,51.523) 23.808,51.523 v1(23.854,51.478) ; U14.106@27.366,82.129 v1(27.366,84.129) ; U14.7@29.366,60.479 v1(29.366,61.644) ; v1(31.741,43.304) R43.2@32.466,43.304 ; v1(32.016,40.429) R51.2@32.741,40.429 ; v1(32.016,41.479) R50.2@32.741,41.479 ; U14.13@32.366,60.479 32.366,61.411 v1@32.743,61.788 ; U14.92@34.366,82.129 34.366,83.379 v1(33.839,83.906) C47.2@33.839,84.429 C48.2@34.866,84.429 C49.2@35.866,84.429 ; U14.19@35.366,60.479 v1(35.366,61.778) ; v1(36.466,43.104) C79.2@37.091,42.479 37.091,41.904 37.941,41.054 U15.9@37.941,40.579 ; R46.2@38.291,43.304 v1(38.291,44.029) ; U14.79@40.866,82.129 C50.2@40.866,84.429 ; R49.2@41.441,43.304 v1(41.441,44.029) ; C67.2@41.866,58.329 42.141,58.604 v1(42.141,59.179) 41.866,59.454 U14.32@41.866,60.479 ; U14.42@45.941,65.054 47.585,65.054 v1(47.616,65.023) ; U14.56@45.941,72.054 v1(47.356,72.054) 47.431,72.129 C55.2@48.166,72.129 ; U14.71@45.941,79.554 46.916,79.554 47.139,79.777 47.139,79.808 47.96,80.629 v1(48.866,80.629) C52.2@49.666,80.629 ; R40.1@49.766,57.929 50.366,57.329 v1(50.616,57.329) 50.716,57.429 C62.1@50.716,58.079
  Top Layer w0.5: v1(19.166,86.879) v1(19.841,86.879) ; C59.2@21.066,61.129 22.066,61.129 v1(22.316,61.379) 22.566,61.629 22.566,61.809 23.211,62.454 U14.144@24.291,62.454 ; v1(27.366,84.129) C46.2@27.366,84.679 ; R59.2@31.066,14.129 v1(31.066,14.779) ; v1(31.841,11.804) R64.2@31.841,11.024 31.841,10.479 31.941,10.379 v1(31.941,9.954) ; v1(34.641,53.016) 35.332,53.016 v1(35.366,53.051)
  Signal Layer 2 w0.3: v1(22.891,51.523) 23.808,51.523 v1(23.854,51.478) ; v1(34.641,53.016) 35.332,53.016 v1(35.366,53.051)
  Signal Layer 2 w0.5: 18.566,86.879 v1(19.166,86.879) v1(19.841,86.879) ; v1(31.841,11.804) 31.841,10.054 v1(31.941,9.954)
  Signal Layer 3 w0.5: v1(13.791,113.604) v1@13.791,113.804 ; 22.866,50.49 22.891,50.515 ; v1(22.891,51.523) 22.891,50.515 ; v1(23.854,51.478) 22.891,50.515
  Signal Layer 3 w0.8: v1(11.741,129.104) 11.741,127.529 v1(12.491,126.779) 11.366,125.654 11.366,115.679 12.591,114.454 v1(13.141,114.454) v1@13.791,113.804 ; v1(13.791,113.604) 13.791,110.229 15.641,108.379 15.641,97.279 15.016,96.654 15.016,93.629 15.916,92.729 15.916,91.629 16.941,90.604 16.941,88.504 18.566,86.879 v1(19.166,86.879) v1(19.841,86.879)
  Bottom Layer w0.3: SB32.2@32.591,76.454 33.116,76.979 v1(33.716,76.979)
  Bottom Layer w0.4: v1(28.71,55.498) 28.489,55.719 28.489,56.276 28.866,56.654
  Bottom Layer w0.5: v1(13.141,114.454) 13.141,114.254 v1(13.791,113.604) ; 18.566,86.879 v1(19.166,86.879) v1(19.841,86.879) ; v1(22.891,51.523) 22.891,50.934 23.475,50.35 SB97.2@23.725,50.35 23.854,50.479 v1(23.854,51.478) ; 28.866,56.654 SB83.1@28.866,57.129 ; v1(31.066,14.779) 31.841,14.004 v1(31.841,11.804) 31.841,10.054 v1(31.941,9.954) ; v1(34.641,53.016) SB92.2@34.641,54.029 35.366,53.304 v1(35.366,53.051) ; v1(48.866,80.629) SB25.2@48.866,81.879 v1(49.841,81.879)
  other v1: 32.841,61.829 40.866,83.879
VDD_SMPS_IN: C65.2 C68.2 SB74.2 SB92.1 U14.16 | length 10.7
  Top Layer w0.3: v1(33.516,62.144) 33.839,61.821 33.839,61.51 33.866,61.483 U14.16@33.866,60.479 33.866,59.454 34.416,58.904
  Top Layer w0.4: C65.2@34.416,58.379 34.416,58.904
  Top Layer w0.5: v1(34.416,56.279) 34.416,57.129 35.068,56.476 v1@35.068,56.376
  Top Layer w0.6: C68.2@34.416,57.129 C65.2@34.416,58.379
  Bottom Layer w0.3: v1@33.509,62.151 SB74.2@33.509,63.153
  Bottom Layer w0.5: v1@33.509,62.151 v1(33.516,62.144) ; v1(34.416,56.279) 34.416,55.894 34.641,55.669 34.641,55.329 ; SB92.1@34.641,55.129 34.641,55.329 ; v1(35.116,56.279) 35.116,55.804 34.641,55.329
VDD_SMPS_IND_OUT: C75.2 L1.2 SB79.2 | length 10.7
  Top Layer w0.5: v1(31.216,55.079) 32.316,55.079 L1.2@32.366,55.129 ; C75.2@32.366,54.079 L1.2@32.366,55.129 ; v1(33.416,54.279) 33.416,54.579 L1.2@32.616,55.379 L1.2@32.366,55.129
  Bottom Layer w0.6: SB79.2@31.966,60.229 31.839,60.102 31.839,59.406 33.416,57.829 v1(33.416,54.279)
VDD_SMPS_OUT: C64.2 L1.1 U14.15 | length 3.9
  Top Layer w0.3: 33.366,59.029 U14.15@33.366,60.479
  Top Layer w0.4: C64.2@33.066,58.379 33.066,58.729 33.366,59.029
  Top Layer w0.5: L1.1@32.616,56.879 L1.1@33.066,57.329
  Top Layer w0.6: L1.1@33.066,57.329 C64.2@33.066,58.379
VDDA: C61.1 C72.1 C73.2 CN10.1 R39.1 R40.2 U14.36 | length 34.2
  Top Layer w0.3: U14.36@43.966,60.479 43.966,59.729 45.366,58.329 R39.1@45.366,58.054 45.891,58.054 46.391,57.554 C73.2@46.391,56.804 C72.1@47.466,56.804 48.366,57.704 R40.2@48.366,57.929 ; C61.1@48.891,59.079 48.366,58.554 R40.2@48.366,57.929 ; v1(55.391,57.454) 53.816,55.879 50.416,55.879 R40.2@48.366,57.929
  Bottom Layer w0.3: v1(55.391,57.454) 55.391,72.464 CN10.1@56.586,73.659
VFBSD: R33.1 R34.2 R35.2 U14.17 | length 103.4
  Top Layer w0.127: R34.2@28.291,85.029 v1(28.291,85.629) R33.1@28.291,86.229 ; U14.17@34.366,60.479 v1(34.366,61.729) ; v1(47.866,76.879) 49.091,76.879 49.566,77.354 R35.2@49.566,77.629
  Signal Layer 3 w0.127: v1(28.291,85.629) 28.291,84.295 27.816,83.82 27.683,83.82 27.492,83.629 20.891,83.629 20.391,83.129 20.391,63.054 20.566,62.879 26.266,62.879 27.041,63.654 31.191,63.654 31.966,62.879 33.909,62.879 34.366,62.422 v1(34.366,61.729) ; v1(33.116,66.611) 33.116,66.629 32.366,67.379 23.866,67.379 23.366,67.879 23.366,78.879 23.866,79.379 35.688,79.379 35.697,79.37 36.035,79.37 36.044,79.379 46.366,79.379 46.616,79.129 46.616,77.879 46.866,77.629 47.116,77.629 v1(47.866,76.879)
  Bottom Layer w0.127: v1(33.116,66.611) 33.4,66.611 34.45,65.561 34.45,65.156 34.336,65.042 34.336,61.759 v1(34.366,61.729)
VIN: C42.2 CN8.15 CN11.24 U12.3 | length 80.6
  Top Layer w0.5: v1@18.266,100.654 U12.3@18.266,101.754 ; U12.3@18.266,101.754 v1(19.641,101.754) v1(19.641,100.629) v1(18.266,100.629) v1(16.541,100.629) C42.2@16.541,101.774 18.246,101.774 U12.3@18.266,101.754
  Top Layer w1: CN11.24@5.786,73.659 CN8.15@10.866,73.659
  Signal Layer 2 w0.4: 1.491,77.379 1.556,77.444 4.501,77.444 4.516,77.429 ; 1.491,80.129 1.636,79.984 3.986,79.984 4.516,79.454 4.516,77.429 ; 1.791,75.404 2.266,74.929 4.161,74.929 ; 4.516,74.929 4.516,77.429
  Signal Layer 2 w0.8: 1.791,75.404 1.491,75.704 1.491,77.379 1.491,80.129 1.491,103.754 2.041,104.304 7.191,104.304 8.451,103.044 11.465,103.044 12.05,102.459 13.337,102.459 13.402,102.524 14.225,102.524 14.495,102.254 15.026,102.254 v1@16.541,100.739
  Signal Layer 2 w1: 4.161,74.929 4.516,74.929 CN11.24@5.786,73.659 CN8.15@10.866,73.659
VOUTVDD: CN6.3 SB97.1 | length 3.2
  Bottom Layer w0.4: v1@22.866,47.654 v1(22.891,47.629) 22.891,48.466 23.675,49.25 SB97.1@23.725,49.25 23.866,49.109 v1(23.866,48.129)
VREFP: C69.1 C70.2 C71.2 R39.2 SB60.2 U14.35 | length 13.7
  Top Layer w0.3: C71.2@42.941,56.929 C69.1@44.016,56.929 ; U14.35@43.366,60.479 v1(43.366,58.879) 43.966,58.279 R39.2@43.966,58.054 43.966,56.979 C69.1@44.016,56.929 ; C70.2@45.316,56.929 C69.1@44.016,56.929
  Bottom Layer w0.3: v1(43.366,58.879) 43.366,61.21 43.811,61.655 43.811,62.738 43.395,63.154 43.395,65.783 SB60.2@43.591,65.979
WAKEUP_KEY: B1.3 B1.4 R67.2 R77.2 U23.1 | length 72.6
  Top Layer w0.12: B1.3@3.017,4.023 B1.4@12.517,4.023 14.56,4.023 U23.1@14.566,4.016 R67.2@14.566,5.029 v1(15.641,5.029)
  Bottom Layer w0.12: v1(15.641,5.029) 16.086,5.474 21.125,5.474 23.026,7.374 23.026,10.639 23.731,11.344 23.731,39.004 26.662,41.935 26.662,42.36 27.936,43.634 27.936,45.166 28.257,45.487 28.257,47.52 28.564,47.827 28.564,53.788 28.98,54.204 R77.2@30.266,54.204
pads on no net: CN1.4 CN5.0 CN5.1 CN5.2 CN5.9 CN8.1 CN11.10 CN11.26 CN11.42 CN11.44 CN11.51 CN11.52 CN11.53 CN11.58 CN11.59 CN11.64 CN11.67 CN12.36 CN12.38 CN12.57 CN12.58 CN12.59 CN12.68 CN12.69 CN13.11 CN13.12 Designator1.1 MIRE-1.1 MIRE-2.1 MIRE-3.1 MIRE-4.1 MIRE-5.1 MIRE-6.1 U1.2 U5.4 U7.A1 U7.A2 U7.A3 U7.A4 U7.A5 U7.A6 U7.A8 U7.A9 U7.A10 U7.A11 U7.A12 U7.A13 U7.B1 U7.B2 U7.B3 U7.B4 U7.B5 U7.B6 U7.B7 U7.B8 U7.B9 U7.B10 U7.B11 U7.B12 U7.B13 U7.B14 U7.B15 U7.C2 U7.C3 U7.C4 U7.C11 U7.C12 U7.C13 U7.C14 U7.C15 U7.D1 U7.D2 U7.D3 U7.D4 U7.D10 U7.D11 U7.D13 U7.D14 U7.E1 U7.E2 U7.E3 U7.E4 U7.E12 U7.E13 U7.E14 U7.E15 U7.F1 U7.F4 U7.F14 U7.G4 U7.G14 U7.G15 U7.H1 U7.H2 U7.H3 U7.H4 U7.H14 U7.H15 U7.J2 U7.J3 U7.J4 U7.K1 U7.K2 U7.K3 U7.K12 U7.K14 U7.K15 U7.L1 U7.L3 U7.L12 U7.L13 U7.L14 U7.L15 U7.M2 U7.M3 U7.M4 U7.M5 U7.M6 U7.M7 U7.M12 U7.M13 U7.M14 U7.M15 U7.N2 U7.N4 U7.N5 U7.N6 U7.N7 U7.N11 U7.N13 U7.N14 U7.N15 U7.P2 U7.P4 U7.P5 U7.P6 U7.P7 U7.P8 U7.P9 U7.P10 U7.P11 U7.P12 U7.P13 U7.P14 U7.P15 U7.R2 U7.R3 U7.R6 U7.R7 U7.R8 U7.R9 U7.R10 U7.R11 U7.R12 U7.R13 U11.3 U14.0 U17.4 U17.5 U17.12 U17.13 U19.5 U24.4

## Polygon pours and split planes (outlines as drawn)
GND on Bottom Layer "GND_L06_P114" (solid, remove dead copper, pour order 114): 20.266,133.254 20.266,108.279 20.441,108.104 25.741,108.104 26.241,107.604 26.241,99.479 26.666,99.054 35.991,99.054 36.991,98.054 36.991,92.304 34.791,90.104 31.091,90.104 29.391,88.404 29.391,85.779 25.866,82.254 25.866,65.679 26.966,64.579 32.583,64.579 34.416,62.746 34.416,53.329 34.141,53.054 29.691,53.054 29.266,52.629 29.266,44.804 29.691,44.379 33.241,44.379 33.791,43.829 33.791,40.354 32.991,39.554 31.191,39.554 30.766,39.129 30.766,37.729 33.316,35.179 33.316,8.779 33.741,8.354 52.091,8.354 52.616,7.829 52.616,0.579 53.141,0.054 68.491,0.054 69.916,1.479 69.916,132.004 68.666,133.254 21.541,133.254
GND on Bottom Layer "GND_L06_P112" (solid, remove dead copper, pour order 112): 1.641,133.354 0.066,131.779 0.066,1.379 1.241,0.204 35.591,0.204 36.041,0.654 36.041,8.329 35.466,8.904 29.516,8.904 28.966,9.454 28.966,30.529 27.816,31.679 27.216,32.279 27.216,40.954 30.266,44.004 30.266,60.104 27.016,63.354 18.541,63.354 18.166,63.729 18.166,65.504 18.516,65.854 21.691,65.854 22.716,66.879 22.716,86.779 25.241,89.304 25.241,99.829 25.216,99.854 16.421,99.854 15.791,100.484 15.791,102.204 16.266,102.679 18.691,102.679 19.091,103.079 19.091,104.929 19.966,105.804 19.966,107.629 20.441,108.104 20.441,133.304 20.391,133.354
1V2_MCU on Bottom Layer "1V2_MCU_L06_P010" (solid, pour order 10): 32.616,63.379 32.616,61.379 29.866,61.379 29.866,63.379
VDD_SMPS_IND_OUT on Bottom Layer "VDD_SMPS_IND_OUT_L06_P002" (solid, pour order 2): 30.866,60.479 30.866,53.879 33.866,53.879 33.866,60.479
5V_VIN on Bottom Layer "5V_VIN_L06_P036" (solid, remove dead copper, pour order 36): 19.341,104.754 20.291,105.704 20.291,107.479 20.641,107.829 25.616,107.829 25.991,107.454 25.991,100.604 25.641,100.254 20.466,100.254 20.266,100.454 20.266,102.404 19.566,103.104 19.341,103.329
VIN on Bottom Layer "VIN_L06_P084" (solid, remove dead copper, pour order 84): 16.491,102.304 16.141,101.954 16.141,100.604 16.466,100.279 19.816,100.279 20.066,100.529 20.066,102.029 19.791,102.304
SHGND on Bottom Layer "SHGND_L06_P056" (solid, remove dead copper, pour order 56): 35.641,17.325 53.369,17.325 53.369,0 35.741,0 35.641,0.004
3V3_VDD on Bottom Layer "3V3_VDD_L06_P080" (solid, remove dead copper, pour order 80): 19.616,65.579 18.766,65.579 18.441,65.254 18.441,64.004 18.791,63.654 22.491,63.654 24.291,65.454 24.291,67.804 25.491,69.004 25.491,82.454 26.416,83.379 29.041,86.004 29.041,88.629 30.891,90.479 34.591,90.479 36.616,92.504 36.616,97.854 35.766,98.704 26.241,98.704 25.891,98.354 25.891,96.679 26.041,96.529 27.141,96.529 27.441,96.229 27.441,90.754 23.016,86.329 23.016,66.729 21.866,65.579 20.616,65.579
VDD_MCU on Bottom Layer "VDD_MCU_L06_P086" (solid, remove dead copper, pour order 86): 32.591,9.154 33.041,9.604 33.041,34.943 30.341,37.643 30.341,39.229 30.991,39.879 32.791,39.879 33.366,40.454 33.366,43.729 33.041,44.054 30.991,44.054 27.541,40.604 27.541,32.479 29.241,30.779 29.241,9.554 29.641,9.154
3V3_PER on Signal Layer 3 "3V3_PER_L04_P116" (solid, remove dead copper, pour order 116): 51.075,39.475 28.125,39.475 26.75,38.1 26.875,37.975 26.875,34.05 28.525,32.4 30.4,32.4 30.4,36.225 31.55,37.375 31.575,37.35 51.075,37.35
3V3_PER on Signal Layer 3 "3V3_PER_L04_P066" (solid, remove dead copper, pour order 66): 31.087,15.712 31.075,15.725 31.085,24.285 30.416,24.954 30.416,35.254 27.391,35.254 27.391,19.104 28.441,18.054 28.441,1.504 28.916,1.029 34.116,1.029 34.666,1.579 34.666,4.7 31.075,8.263 31.075,15.7
NetC90_2 on Signal Layer 3 "NETC90_2_L04_P048" (solid, remove dead copper, pour order 48): 33.941,23.129 33.091,22.279 33.091,17.779 35.116,15.754 48.341,15.754 49.241,16.654 49.241,22.479 48.591,23.129
GND on Signal Layer 3 "GND_L04_P104" (solid, remove dead copper, pour order 104): 21.391,96.254 21.766,95.879 21.766,91.179 21.541,90.954 20.591,90.954 19.466,92.079 19.466,95.654 20.066,96.254
1V2_MCU on Signal Layer 3 "1V2_MCU_L04_P006" (solid, remove dead copper, pour order 6): 26.531,62.879 27.131,63.479 31.166,63.479 31.766,62.879 32.616,62.879 32.616,61.879 21.366,61.879 21.366,51.879 19.616,51.879 19.616,62.879
VCAP on Signal Layer 3 "VCAP_L04_P012" (solid, remove dead copper, pour order 12): 31.366,64.379 31.366,66.129 29.641,66.129 29.641,64.379 21.866,64.379 21.866,80.879 47.866,80.879 47.866,77.629 46.616,77.629 46.616,79.379 23.366,79.379 23.366,67.129 32.859,67.129 32.859,64.379
VIN on Signal Layer 3 "VIN_L04_P040" (solid, remove dead copper, pour order 40): 19.791,100.254 20.041,100.504 20.041,102.004 19.916,102.129 16.416,102.129 16.266,101.979 16.266,100.429 16.441,100.254
5V_VIN on Signal Layer 3 "5V_VIN_L04_P032" (solid, remove dead copper, pour order 32): 19.341,104.754 20.291,105.704 20.291,107.479 20.641,107.829 25.616,107.829 25.991,107.454 25.991,100.604 25.641,100.254 20.466,100.254 20.266,100.454 20.266,102.404 19.566,103.104 19.341,103.329
VDD_LDO on Signal Layer 3 "VDD_LDO_L04_P008" (solid, remove dead copper, pour order 8): 26.189,63.029 26.969,63.81 26.969,63.827 31.272,63.827 31.365,63.919 31.365,66.282 29.791,66.282 29.791,64.379 21.866,64.379 21.866,80.879 47.866,80.879 47.866,79.129 48.616,79.129 48.616,83.629 20.366,83.629 20.366,63.029
3V3 on Signal Layer 3 "3V3_L04_P072" (solid, remove dead copper, pour order 72): 53.116,107.229 53.391,106.954 53.391,96.904 53.116,96.629 50.641,96.629 50.416,96.854 50.416,97.154 52.091,98.829 52.091,107.004 52.316,107.229
NetC84_2 on Signal Layer 3 "NETC84_2_L04_P046" (solid, remove dead copper, pour order 46): 31.891,37.104 30.891,36.104 30.891,25.154 32.316,23.729 48.316,23.729 49.116,24.529 49.116,36.604 48.616,37.104
1V2_VOUTCORE on Signal Layer 3 "1V2_VOUTCORE_L04_P018" (solid, remove dead copper, pour order 18): 15.946,50.879 21.749,50.879 21.749,45.084 15.946,45.084
VOUTVDD on Signal Layer 3 "VOUTVDD_L04_P030" (solid, remove dead copper, pour order 30): 21.661,49.529 24.201,49.529 24.201,41.909 17.851,41.909 17.851,45.084 21.661,45.084
5V_USB_CHGR on Signal Layer 3 "5V_USB_CHGR_L04_P042" (solid, remove dead copper, pour order 42): 58.3,113.488 57.241,112.429 50.141,112.429 35.641,126.929 35.641,129.779 36.741,130.879 62.641,130.879 63.716,129.804 63.716,124.829 63.016,124.129 59.229,124.129 58.3,123.2
5V on Signal Layer 3 "5V_L04_P070" (solid, remove dead copper, pour order 70): 1.616,113.729 1.616,114.129 2.116,114.629 4.816,114.629 5.316,114.129 5.316,95.454 9.916,90.854 9.916,83.354 10.466,82.804 12.341,82.804 12.556,82.589 12.556,79.819 12.366,79.629 10.491,79.629 9.891,79.029 9.891,76.554 7.741,74.404 7.741,11.254 6.716,10.229 1.216,10.229 0.891,10.554 0.891,80.104 2.141,81.354 4.341,81.354 6.616,83.629 6.616,84.904 5.891,85.629 2.191,85.629 1.616,86.204
3V3_VDD on Signal Layer 3 "3V3_VDD_L04_P100" (solid, remove dead copper, pour order 100): 19.016,65.129 19.366,64.779 19.366,62.379 17.891,60.904 17.891,53.354 15.616,51.079 15.616,42.879 16.941,41.554 20.816,41.554 21.441,40.929 21.441,16.004 12.716,7.279 8.491,7.279 7.591,8.179 7.616,8.204 7.616,9.304 16.366,18.054 16.366,33.229 11.496,38.099 9.971,38.099 8.516,39.554 8.516,64.179 10.316,65.979 18.166,65.979
GND on Signal Layer 3 "GND_L04_P000" (solid, remove dead copper, pour order 0): 6.591,9.904 0.191,9.904 0.091,9.804 0.091,1.629 1.691,0.029 28.591,0.029 28.741,0.179 28.741,0.854 28.191,1.404 28.191,4.329 28.991,5.129 29.316,5.129 29.316,13.829 29.316,16.079 26.366,19.029 26.366,40.154 26.366,41.354 26.041,41.679 21.991,41.679 21.666,41.354 21.666,15.829 12.941,7.104 8.091,7.104 7.391,7.804 7.391,9.104
3V3_STLK on Signal Layer 3 "3V3_STLK_L04_P044" (solid, remove dead copper, pour order 44): 33.866,132.179 34.691,131.354 34.691,128.554 34.716,128.529 34.716,126.504 44.966,116.254 44.966,110.404 43.766,109.204 15.766,109.204 14.541,110.429 14.541,131.429 15.291,132.179
3V3_PER on Signal Layer 3 "3V3_PER_L04_P074" (solid, remove dead copper, pour order 74): 39.166,108.904 38.791,108.529 38.791,104.679 38.191,104.079 35.091,104.079 30.341,99.329 30.341,97.254 46.441,97.254 48.891,94.804 51.516,94.804 51.516,95.379 46.416,100.479 46.416,104.604 44.841,106.179 43.291,106.179 40.591,108.879 40.591,108.904
3V3_PER on Signal Layer 3 "3V3_PER_L04_P076" (solid, remove dead copper, pour order 76): 34.541,101.129 30.641,97.229 18.841,97.229 17.166,95.554 17.166,94.554 18.166,93.554 18.166,91.729 20.341,89.554 20.341,88.154 19.966,87.779 18.491,87.779 17.566,88.704 17.566,89.979 16.516,91.029 16.516,92.929 15.541,93.904 15.541,96.254 18.741,99.454 30.016,99.454 34.391,103.829 34.541,103.679
3V3_PER on Signal Layer 3 "3V3_PER_L04_P078" (solid, remove dead copper, pour order 78): 53.726,37.428 53.648,37.35 50.675,37.35 50.675,39.05 59.866,48.241 59.866,50.404 53.491,56.779 53.491,87.029 51.366,89.154 51.366,92.329 48.016,95.679 54.091,95.679 59.141,90.629 59.141,72.279 63.216,68.204 63.216,42.354 58.306,37.444 53.744,37.444
GND on Signal Layer 3 "GND_L04_P110" (solid, remove dead copper, pour order 110): 52.991,55.404 54.391,55.404 59.491,50.304 59.491,47.3 53,47.3 52.991,55.129
GND on Signal Layer 3 "GND_L04_P108" (solid, remove dead copper, pour order 108): 8.241,37.229 11.736,37.229 15.791,33.174 15.791,18.279 8.991,11.479 8.241,11.479
GND on Signal Layer 3 "GND_L04_P106" (solid, remove dead copper, pour order 106): 34.091,133.054 34.091,132.504 35.391,131.204 62.816,131.204 64.091,129.929 64.091,124.654 63.191,123.754 61.616,123.754 60.8,122.938 60.8,113.6 59.204,112.004 49.866,112.004 47.666,114.204 45.866,114.204 45.441,113.779 45.441,110.329 43.916,108.804 41.766,108.804 41.491,108.529 41.491,108.254 43.391,106.354 45.041,106.354 46.741,104.654 46.741,100.654 49.616,97.779 50.666,97.779 51.816,98.929 51.816,107.179 52.116,107.479 53.241,107.479 53.641,107.079 53.641,96.579 59.866,90.354 59.866,72.404 63.991,68.279 63.991,42.541 52.541,31.091 52.541,0.229 52.666,0.104 68.416,0.104 69.966,1.654 69.966,131.879 68.691,133.154 34.191,133.154
VDD_MCU on Signal Layer 3 "VDD_MCU_L04_P016" (solid, remove dead copper, pour order 16): 25.266,50.129 25.291,50.104 25.291,41.579 27.166,39.704 50.816,39.704 52.744,41.631 52.744,87.162 50.991,88.915 50.991,91.904 47.516,95.379 21.866,95.379 21.866,50.129
GND on Signal Layer 3 "GND_L04_P102" (solid, remove dead copper, pour order 102): 15.641,133.179 14.116,131.654 14.116,110.154 15.141,109.129 15.141,109.104 15.316,108.929 38.166,108.929 38.491,108.604 38.491,105.779 38.191,105.479 34.566,105.479 33.516,104.429 33.516,103.354 29.891,99.729 26.616,99.729 26.241,100.104 26.241,107.604 25.766,108.079 20.441,108.079 20.016,107.654 20.016,106.004 19.066,105.054 19.066,103.229 19.491,102.804 19.491,102.379 16.316,102.379 16.091,102.154 16.091,97.729 15.016,96.654 15.016,93.629 15.916,92.729 15.916,91.229 16.941,90.204 16.941,88.229 17.791,87.379 20.716,87.379 21.591,86.504 21.591,84.804 20.166,83.379 20.166,67.179 19.341,66.354 9.966,66.354 8.866,65.254 8.816,65.304 8.066,65.304 8.066,74.229 10.066,76.229 10.066,78.379 10.966,79.279 12.466,79.279 12.966,79.779 12.966,82.679 12.591,83.054 11.091,83.054 10.216,83.929 10.216,91.229 5.866,95.579 5.866,114.279 5.091,115.054 1.966,115.054 1.591,114.679 0.116,114.679 0.116,131.829 1.466,133.179
5V on Top Layer "5V_L01_P064" (solid, remove dead copper, pour order 64): 25.616,14.429 25.466,14.279 25.466,12.929 25.691,12.704 27.941,12.704 28.166,12.929 28.166,13.629 27.941,13.854 27.291,13.854 26.716,14.429
VIN on Top Layer "VIN_L01_P026" (solid, remove dead copper, pour order 26): 16.041,102.829 15.816,102.604 15.816,100.504 16.041,100.279 19.816,100.279 20.016,100.479 20.016,102.604 19.791,102.829
GND on Top Layer "GND_L01_P024" (solid, remove dead copper, pour order 24): 15.541,100.504 15.316,100.279 13.891,100.279 13.666,100.504 13.666,107.429 14.041,107.804 19.966,107.804 19.966,105.604 19.741,105.379 15.816,105.379 15.541,105.104
5V_VIN on Top Layer "5V_VIN_L01_P028" (solid, remove dead copper, pour order 28): 16.091,105.154 15.816,104.879 15.816,103.354 16.091,103.079 19.966,103.079 20.291,102.754 20.291,100.479 20.491,100.279 25.641,100.279 25.966,100.604 25.966,107.429 25.591,107.804 20.641,107.804 20.291,107.454 20.291,105.454 19.991,105.154
GND on Top Layer "GND_L01_P022" (solid, remove dead copper, pour order 22): 43.791,133.304 43.791,126.679 42.666,125.554 32.616,125.554 31.991,124.929 31.991,123.179 32.866,122.304 50.741,122.304 54.366,125.929 54.366,133.304
5V on Top Layer "5V_L01_P038" (solid, remove dead copper, pour order 38): 59.189,124.529 58.525,123.865 58.525,113.518 59.339,112.704 62.941,112.704 63.716,111.929 63.716,108.629 63.566,108.479 60.166,108.479 59.991,108.304 59.991,107.554 60.291,107.254 67.116,107.254 67.666,107.804 67.666,118.154 67.366,118.454 64.866,118.454 64.116,119.204 64.116,123.929 63.516,124.529
USB_FS_VBUS on Top Layer "USB_FS_VBUS_L01_P068" (solid, remove dead copper, pour order 68): 27.991,12.079 28.266,11.804 28.266,9.154 26.916,7.804 26.116,7.804 24.941,6.629 24.941,4.554 23.666,3.279 21.966,3.279 21.841,3.404 21.841,5.254 25.666,9.079 25.666,10.779 25.816,10.929 26.816,10.929 27.016,11.129 27.016,11.904 27.191,12.079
